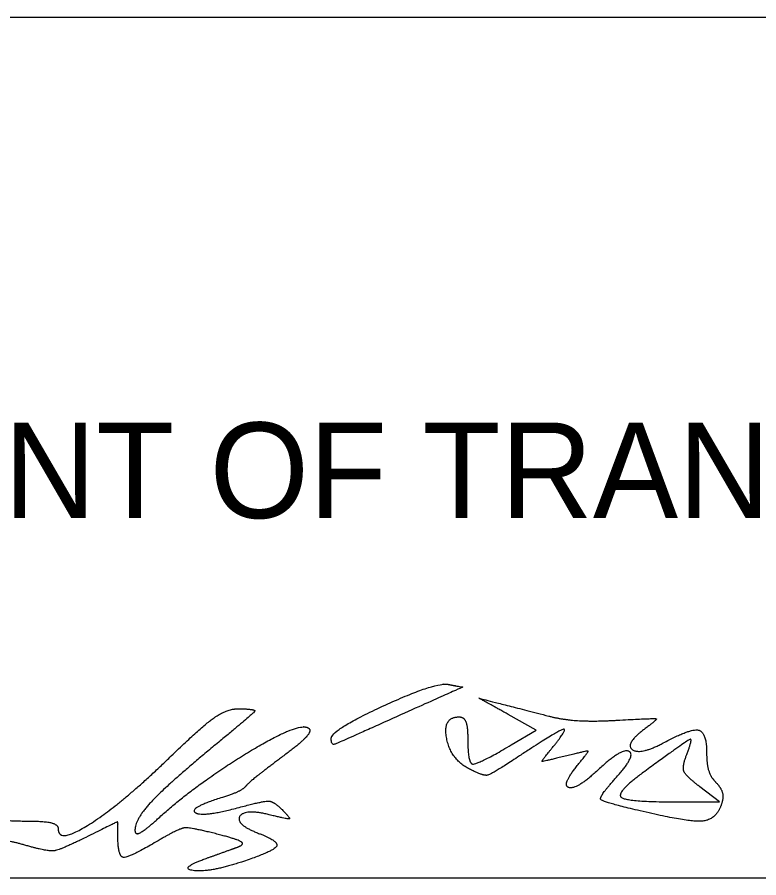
# Model space of a CAD drawing. Extents: x -12 to 34, y 0 to 22.
# Drawn here: x 26.669 to 27.756, y 7.295 to 8.555 of the extents above; entities that cross this region are included whole.
import ezdxf

# ---------------------------------------------------------------- set-up
doc = ezdxf.new("R2010")
doc.units = 0
doc.layers.add('GM_X_Adjacent_County', color=7, linetype='Continuous')
doc.layers.add('GM_X_Township', color=7, linetype='Continuous')

msp = doc.modelspace()

# ---------------------------------------------------------------- linework, layer by layer
at = {"layer": 'GM_X_Adjacent_County'}
for p, q in [((27.1295, 7.4988), (27.1295, 7.4988)), ((27.582, 7.3926), (27.582, 7.3926))]:
    msp.add_line(p, q, dxfattribs=at)
for points in [[(27.3933, 7.4892), (27.4297, 7.5107), (27.3889, 7.5337)], [(27.642, 7.4057), (27.6982, 7.4058), (27.6695, 7.4279)]]:
    msp.add_lwpolyline(points, dxfattribs=at)
for points in [[(27.1295, 7.4988), (27.1295, 7.5112), (27.2823, 7.5815), (27.3012, 7.5778)], [(27.3012, 7.5778), (27.3219, 7.5738), (27.3226, 7.5742), (27.201, 7.5196)], [(27.3889, 7.5337), (27.3461, 7.5578), (27.3452, 7.5578), (27.4482, 7.5314)], [(26.8951, 7.473), (26.9403, 7.5168), (26.9774, 7.5425), (26.9951, 7.5422)], [(26.9951, 7.5422), (27.0194, 7.5417), (27.0156, 7.5353), (26.967, 7.4953)], [(27.3305, 7.4547), (27.304, 7.4689), (27.293, 7.5302), (27.317, 7.5302)], [(27.317, 7.5302), (27.3238, 7.5302), (27.3295, 7.5162), (27.3295, 7.499)], [(27.4482, 7.5314), (27.4688, 7.5261), (27.5138, 7.5234), (27.5482, 7.5253)], [(27.5482, 7.5253), (27.6031, 7.5284), (27.608, 7.5268), (27.5881, 7.512)], [(26.8763, 7.3818), (26.93, 7.4307), (27.0769, 7.5207), (27.0938, 7.515)], [(27.0938, 7.515), (27.1022, 7.5122), (27.087, 7.4935), (27.0599, 7.4733)], [(27.201, 7.5196), (27.1385, 7.4914), (27.1295, 7.4888), (27.1295, 7.4988)], [(27.4529, 7.4844), (27.4773, 7.514), (27.4615, 7.5102), (27.4052, 7.473)], [(27.5881, 7.512), (27.5593, 7.4905), (27.5822, 7.4741), (27.6159, 7.4921)], [(27.6159, 7.4921), (27.6561, 7.5137), (27.6795, 7.5079), (27.6795, 7.4765)], [(26.967, 7.4953), (26.8929, 7.4343), (26.842, 7.3808), (26.842, 7.3641)], [(27.3295, 7.499), (27.3295, 7.4622), (27.3438, 7.46), (27.3933, 7.4892)], [(27.6497, 7.4734), (27.6596, 7.4992), (27.6514, 7.4961), (27.5888, 7.4505)], [(27.4723, 7.4727), (27.4392, 7.4644), (27.4374, 7.4656), (27.4529, 7.4844)], [(27.4924, 7.462), (27.507, 7.4796), (27.5047, 7.4808), (27.4723, 7.4727)], [(27.5462, 7.4405), (27.5767, 7.4742), (27.5551, 7.4851), (27.5211, 7.4532)], [(27.6795, 7.4765), (27.6795, 7.4607), (27.6858, 7.4414), (27.6936, 7.4336)], [(26.7295, 7.3662), (26.7295, 7.3434), (26.8248, 7.4048), (26.8951, 7.473)], [(27.0599, 7.4733), (27.0328, 7.4531), (27.0079, 7.4331), (27.0045, 7.4289)], [(27.4052, 7.473), (27.3652, 7.4465), (27.3519, 7.4432), (27.3305, 7.4547)], [(27.5211, 7.4532), (27.4892, 7.4232), (27.4661, 7.4303), (27.4924, 7.462)], [(27.6695, 7.4279), (27.6491, 7.4436), (27.6434, 7.4568), (27.6497, 7.4734)], [(27.5888, 7.4505), (27.5461, 7.4194), (27.5626, 7.4056), (27.642, 7.4057)], [(27.582, 7.3926), (27.5272, 7.4055), (27.5215, 7.4132), (27.5462, 7.4405)], [(27.0045, 7.4289), (27.001, 7.4246), (26.9856, 7.4171), (26.9701, 7.4123)], [(27.6936, 7.4336), (27.7014, 7.4258), (27.7044, 7.4106), (27.7003, 7.3998)], [(26.9701, 7.4123), (26.9206, 7.3969), (26.9401, 7.3832), (26.9919, 7.397)], [(26.9919, 7.397), (27.0302, 7.4073), (27.0455, 7.4066), (27.0575, 7.3944)], [(27.7003, 7.3998), (27.6922, 7.3787), (27.651, 7.3762), (27.582, 7.3926)], [(27.0388, 7.3869), (27.0021, 7.396), (26.9889, 7.3729), (27.0232, 7.3597)], [(27.0575, 7.3944), (27.0702, 7.3815), (27.0666, 7.3801), (27.0388, 7.3869)], [(26.6332, 7.3849), (26.6371, 7.3809), (26.6604, 7.3777), (26.6849, 7.3777)], [(26.6849, 7.3777), (26.7094, 7.3777), (26.7295, 7.3725), (26.7295, 7.3662)], [(26.817, 7.3537), (26.817, 7.3766), (26.8159, 7.3766), (26.7698, 7.3537)], [(26.842, 7.3641), (26.842, 7.3566), (26.8574, 7.3646), (26.8763, 7.3818)], [(26.9621, 7.3587), (26.9233, 7.3685), (26.9065, 7.3669), (26.8789, 7.3506)], [(26.6807, 7.3424), (26.6538, 7.3501), (26.6307, 7.3501), (26.6162, 7.3423)], [(26.7698, 7.3537), (26.7324, 7.3352), (26.7138, 7.3329), (26.6807, 7.3424)], [(26.8789, 7.3506), (26.8339, 7.324), (26.817, 7.3249), (26.817, 7.3537)], [(26.992, 7.3394), (27.0034, 7.3436), (26.9917, 7.3511), (26.9621, 7.3587)], [(27.0232, 7.3597), (27.0538, 7.348), (27.0449, 7.3331), (26.9981, 7.3177)], [(26.9482, 7.3237), (26.962, 7.3286), (26.9817, 7.3357), (26.992, 7.3394)], [(26.9981, 7.3177), (26.9515, 7.3023), (26.9042, 7.308), (26.9482, 7.3237)]]:
    msp.add_open_spline(points, degree=2, dxfattribs=at)
at = {"layer": 'GM_X_Township'}
for p, q in [((24.5279, 8.555), (28.0279, 8.555)), ((24.5279, 7.2946), (28.0279, 7.2946))]:
    msp.add_line(p, q, dxfattribs=at)

# ---------------------------------------------------------------- texts
at = {"layer": 'GM_X_Adjacent_County'}
msp.add_text('DIRECTOR, DEPARTMENT OF TRANSPORTATION', height=0.14, dxfattribs=at).set_placement((24.5279, 7.8214))

doc.saveas('drawing.dxf')
